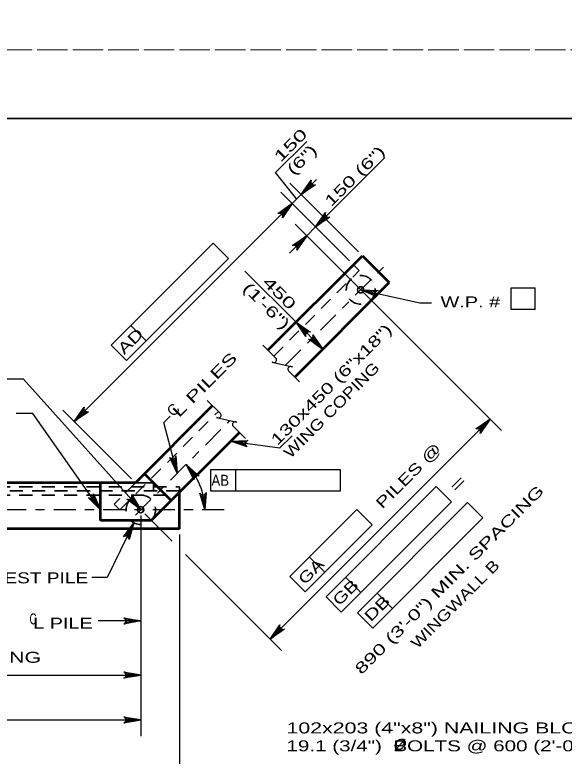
# Model space of a CAD drawing. Extents: x -6.4 to 73.1, y -66 to 0.
# Drawn here: x 16.4 to 22.39, y -29.71 to -21.62 of the extents above; entities that cross this region are included whole.
import ezdxf
from ezdxf.enums import TextEntityAlignment as Align

# ---------------------------------------------------------------- set-up
doc = ezdxf.new("R2010")
doc.units = 0
doc.header["$LTSCALE"] = 0.048
for name, pattern in [('DOT_DASHED', [7.7, 5, -1.2, 0.3, -1.2]), ('LONG_DASHED', [7.5, 6, -1.5]), ('MEDIUM_DASHED', [4.5, 3, -1.5])]:
    doc.linetypes.add(name, pattern=pattern)
for name, color, linetype, lineweight in [('1', 7, 'Continuous', 13), ('2', 7, 'Continuous', 53), ('4', 7, 'Continuous', 25), ('5', 7, 'Continuous', 25), ('63', 7, 'LONG_DASHED', 13)]:
    doc.layers.add(name, color=color, linetype=linetype, lineweight=lineweight)

msp = doc.modelspace()

# ---------------------------------------------------------------- hatches: boundary and pattern name
at = {"layer": '2'}
msp.add_hatch(color=256, dxfattribs=at).paths.add_polyline_path([(17.33158, -27.02208), (17.27175, -26.91983), (17.25558, -26.93108)])
at = {"layer": '4'}
for points in [[(20.171, -24.6215), (20.28425, -24.6565), (20.2885, -24.63725)], [(18.75042, -26.27408), (18.86608, -26.29992), (18.86875, -26.28042)], [(17.77042, -27.02208), (17.69892, -26.92758), (17.68425, -26.94067)]]:
    msp.add_hatch(color=256, dxfattribs=at).paths.add_polyline_path(points)
at = {"layer": '5'}
for points in [[(19.59108, -23.48475), (19.61892, -23.51258), (19.52142, -23.58217)], [(19.32658, -23.74925), (19.35442, -23.77708), (19.424, -23.67967)], [(19.74783, -23.83642), (19.77575, -23.86433), (19.67825, -23.93392)], [(19.48342, -24.10092), (19.51125, -24.12875), (19.58083, -24.03133)], [(19.56208, -25.04483), (19.53425, -25.07267), (19.46467, -24.97525)], [(19.68733, -25.17008), (19.6595, -25.19792), (19.75692, -25.2675)], [(17.11458, -25.96125), (17.14242, -25.98908), (17.04492, -26.05875)], [(21.48442, -26.10192), (21.51225, -26.12975), (21.58183, -26.03233)], [(18.15733, -26.50475), (18.11933, -26.51483), (18.1685, -26.624)], [(17.65225, -28.25575), (17.65225, -28.21642), (17.77042, -28.23608)], [(19.25083, -28.3355), (19.27867, -28.36333), (19.18125, -28.43292)], [(17.65225, -28.80667), (17.65225, -28.84608), (17.77042, -28.82633)], [(17.65225, -29.297), (17.65225, -29.33642), (17.77042, -29.31667)]]:
    msp.add_hatch(color=256, dxfattribs=at).paths.add_polyline_path(points)

# ---------------------------------------------------------------- linework, layer by layer
at = {"layer": '1', "lineweight": 35}
msp.add_lwpolyline([(1.75, -43.25), (33.25, -43.25), (33.25, -22.75), (1.75, -22.75)], close=True, dxfattribs=at)
at = {"layer": '2'}
for p, q in [((19.15867, -25.28117), (20.18958, -24.25033)), ((20.18958, -24.25033), (20.48183, -24.54258)), ((19.451, -25.5735), (20.48183, -24.54258)), ((17.71308, -26.72683), (18.55425, -25.88558)), ((17.88425, -27.14017), (18.84658, -26.17792)), ((18.10283, -26.92167), (17.8105, -26.62942)), ((17.71308, -26.72683), (7.85033, -26.72683)), ((17.33158, -27.14017), (17.33158, -26.72683)), ((18.19242, -27.22875), (18.19242, -26.832)), ((17.88425, -27.14017), (17.33158, -27.14017)), ((18.19242, -27.22875), (7.41692, -27.22875))]:
    msp.add_line(p, q, dxfattribs=at)
at = {"layer": '2', "lineweight": 25}
msp.add_lwpolyline([(17.33158, -27.02208), (16.59375, -25.97225), (16.40908, -25.97225)], dxfattribs=at)
msp.add_lwpolyline([(17.33158, -27.02208), (17.27175, -26.91983), (17.25558, -26.93108)], close=True, dxfattribs=at)
at = {"layer": '4', "linetype": 'MEDIUM_DASHED', "lineweight": 35}
for p, q in [((20.09217, -24.34775), (20.15475, -24.41042)), ((19.22133, -25.34383), (20.15475, -24.41042)), ((17.54308, -27.02208), (18.61692, -25.94825)), ((7.41692, -26.77275), (18.19242, -26.77275)), ((17.71308, -26.72683), (17.48042, -26.9595)), ((18.19242, -26.81542), (7.41692, -26.81542)), ((7.41692, -26.86133), (18.19242, -26.86133)), ((17.54308, -27.02208), (17.48042, -26.9595))]:
    msp.add_line(p, q, dxfattribs=at)
at = {"layer": '4', "lineweight": 35}
for p, q in [((17.90867, -26.72683), (17.71308, -26.72683)), ((17.90867, -26.81542), (17.90867, -26.72683)), ((18.19242, -26.832), (18.19242, -26.77275))]:
    msp.add_line(p, q, dxfattribs=at)
at = {"layer": '4'}
for points in [[(20.171, -24.6215), (20.81575, -24.7635), (20.94467, -24.7635)], [(17.77042, -27.02208), (16.49158, -25.59475), (16.30075, -25.59475)], [(18.75042, -26.27408), (19.28683, -26.34758), (19.42133, -26.21325)]]:
    msp.add_lwpolyline(points, dxfattribs=at)
for points in [[(20.171, -24.6215), (20.28425, -24.6565), (20.2885, -24.63725)], [(18.75042, -26.27408), (18.86608, -26.29992), (18.86875, -26.28042)], [(17.77042, -27.02208), (17.69892, -26.92758), (17.68425, -26.94067)]]:
    msp.add_lwpolyline(points, close=True, dxfattribs=at)
at = {"layer": '4', "linetype": 'MEDIUM_DASHED', "lineweight": 35}
for centre, radius in [((20.17105, -24.62149), 0.15748), ((17.77044, -27.02209), 0.16076)]:
    msp.add_circle(centre, radius, dxfattribs=at)
at = {"layer": '5'}
for p, q in [((19.67833, -23.93383), (20.435, -23.17717)), ((20.14608, -24.20683), (19.39617, -23.45692)), ((19.5215, -23.58217), (19.6885, -23.41517)), ((20.04867, -24.30425), (19.29875, -23.55433)), ((19.32658, -23.77708), (19.52142, -23.58217)), ((17.045, -26.05867), (19.424, -23.67967)), ((19.3405, -23.76317), (19.257, -23.84667)), ((20.04867, -24.30425), (19.553, -23.80858)), ((19.67825, -23.93392), (19.58083, -24.03133)), ((19.58083, -24.03133), (19.39225, -24.21992)), ((17.44725, -25.22467), (18.56083, -24.11117)), ((18.56083, -24.11117), (18.72783, -24.27817)), ((17.61433, -25.39175), (18.72783, -24.27817)), ((19.46467, -24.97525), (18.90508, -24.41567)), ((21.81158, -24.601), (22.07525, -24.601)), ((22.07525, -24.83725), (22.07525, -24.601)), ((19.48858, -24.95125), (19.58992, -24.84992)), ((19.75692, -25.26758), (19.46467, -24.97517)), ((17.66117, -25.01083), (17.82817, -25.17783)), ((19.78092, -25.24358), (19.88225, -25.14225)), ((17.44725, -25.22467), (17.61433, -25.39175)), ((19.101, -25.2235), (19.24442, -25.36692)), ((19.38183, -25.50425), (19.504, -25.6265)), ((18.49625, -25.8275), (18.63967, -25.971)), ((17.66958, -26.68333), (16.91967, -25.93342)), ((18.02225, -26.07025), (18.09158, -26.001)), ((19.18125, -28.43292), (21.58183, -26.03233)), ((18.1685, -26.624), (18.02225, -26.07025)), ((18.777, -26.10833), (18.913, -26.24433)), ((17.66958, -26.68333), (17.17392, -26.18767)), ((18.534, -26.58358), (19.946, -26.58358)), ((18.534, -26.81983), (18.534, -26.58358)), ((18.80775, -26.81983), (18.80775, -26.58358)), ((19.946, -26.58358), (19.946, -26.81983)), ((19.79192, -27.97125), (20.99458, -26.76858)), ((20.99458, -26.76858), (21.16158, -26.93567)), ((19.946, -26.81983), (18.534, -26.81983)), ((19.95892, -28.13825), (21.16158, -26.93567)), ((20.13475, -28.14683), (21.33742, -26.94417)), ((21.33742, -26.94417), (21.50442, -27.11125)), ((19.39633, -27.75175), (20.12992, -27.01808)), ((20.12992, -27.01808), (20.297, -27.18517)), ((17.77042, -27.08358), (17.77042, -29.49383)), ((17.814, -27.06558), (18.11467, -27.36633)), ((20.30183, -28.31383), (21.50442, -27.11125)), ((17.69492, -27.164), (17.40408, -27.75983)), ((19.56333, -27.91875), (20.297, -27.18517)), ((18.19242, -27.29033), (18.19242, -30.05967)), ((18.25933, -27.51092), (19.30658, -28.55825)), ((19.61017, -27.53783), (19.77725, -27.70492)), ((19.39633, -27.75175), (19.56333, -27.91875)), ((20.00575, -27.75733), (20.17283, -27.92442)), ((17.40408, -27.75983), (17.23592, -27.75983)), ((19.79192, -27.97125), (19.95892, -28.13825)), ((20.34867, -27.933), (20.51567, -28.1)), ((20.13475, -28.14683), (20.30183, -28.31383)), ((17.77042, -28.23608), (17.30583, -28.23608)), ((7.78525, -28.82633), (17.77042, -28.82633)), ((12.94308, -29.31667), (17.77042, -29.31667))]:
    msp.add_line(p, q, dxfattribs=at)
at = {"layer": '5', "linetype": 'DOT_DASHED'}
for p, q in [((19.34817, -25.44433), (20.42042, -24.37208)), ((17.71208, -27.08042), (18.744, -26.0485)), ((18.68125, -27.02208), (6.96517, -27.02208))]:
    msp.add_line(p, q, dxfattribs=at)
at = {"layer": '5', "lineweight": 35}
msp.add_line((20.54425, -29.64892), (20.65625, -29.52625), dxfattribs=at)
at = {"layer": '5'}
for points in [[(19.47258, -23.63108), (19.24133, -23.34033), (19.58133, -23.00033)], [(19.5215, -23.58217), (19.62858, -23.42567), (19.6255, -23.44283), (19.62908, -23.45692), (19.63642, -23.46725), (19.64675, -23.47458), (19.66083, -23.47817), (19.678, -23.47508), (19.5215, -23.58217), (19.66083, -23.47817), (19.64675, -23.47458), (19.5215, -23.58217), (19.63642, -23.46725), (19.62908, -23.45692), (19.5215, -23.58217), (19.6255, -23.44283)], [(19.424, -23.67967), (19.31692, -23.83617), (19.32, -23.819), (19.31642, -23.80492), (19.30908, -23.79458), (19.29875, -23.78725), (19.28467, -23.78367), (19.2675, -23.78675), (19.424, -23.67967), (19.28467, -23.78367), (19.29875, -23.78725), (19.424, -23.67967), (19.30908, -23.79458), (19.31642, -23.80492), (19.424, -23.67967), (19.32, -23.819)], [(19.67833, -23.93383), (19.78542, -23.77733), (19.78233, -23.7945), (19.78592, -23.80858), (19.79325, -23.81892), (19.80358, -23.82625), (19.81767, -23.82983), (19.83483, -23.82675), (19.67833, -23.93383), (19.81767, -23.82983), (19.80358, -23.82625), (19.67833, -23.93383), (19.79325, -23.81892), (19.78592, -23.80858), (19.67833, -23.93383), (19.78233, -23.7945)], [(19.45567, -23.90608), (20.61533, -25.06575), (21.70725, -26.15758)], [(19.58083, -24.03133), (19.47375, -24.18783), (19.47683, -24.17067), (19.47325, -24.15658), (19.46592, -24.14625), (19.45558, -24.13892), (19.4415, -24.13533), (19.42433, -24.13842), (19.58083, -24.03133), (19.4415, -24.13533), (19.45558, -24.13892), (19.58083, -24.03133), (19.46592, -24.14625), (19.47325, -24.15658), (19.58083, -24.03133), (19.47683, -24.17067)], [(22.07525, -24.83725), (21.81158, -24.83725), (21.81158, -24.601)], [(20.171, -24.6215), (20.36058, -24.6275), (20.34442, -24.63408), (20.3345, -24.64467), (20.32967, -24.65642), (20.32908, -24.66908), (20.33367, -24.68292), (20.3455, -24.69575), (20.171, -24.6215), (20.33367, -24.68292), (20.32908, -24.66908), (20.171, -24.6215), (20.32967, -24.65642), (20.3345, -24.64467), (20.171, -24.6215), (20.34442, -24.63408)], [(19.46467, -24.97517), (19.62117, -25.08233), (19.604, -25.07917), (19.58992, -25.08275), (19.5795, -25.09008), (19.57225, -25.10042), (19.56858, -25.1145), (19.57175, -25.13175), (19.46467, -24.97517), (19.56858, -25.1145), (19.57225, -25.10042), (19.46467, -24.97517), (19.5795, -25.09008), (19.58992, -25.08275), (19.46467, -24.97517), (19.604, -25.07917)], [(19.75692, -25.26758), (19.60042, -25.16042), (19.61758, -25.16358), (19.63167, -25.16), (19.64208, -25.15267), (19.64933, -25.14233), (19.653, -25.12825), (19.64983, -25.111), (19.75692, -25.26758), (19.653, -25.12825), (19.64933, -25.14233), (19.75692, -25.26758), (19.64208, -25.15267), (19.63167, -25.16), (19.75692, -25.26758), (19.61758, -25.16358)], [(19.217, -25.41442), (19.20325, -25.41125), (19.42483, -25.46183), (19.41, -25.45842)], [(17.045, -26.05867), (17.15208, -25.90217), (17.149, -25.91933), (17.15258, -25.93342), (17.15992, -25.94375), (17.17025, -25.95108), (17.18433, -25.95467), (17.2015, -25.95158), (17.045, -26.05867), (17.18433, -25.95467), (17.17025, -25.95108), (17.045, -26.05867), (17.15992, -25.94375), (17.15258, -25.93342), (17.045, -26.05867), (17.149, -25.91933)], [(18.61225, -26.0185), (18.5985, -26.01525), (18.82008, -26.06583), (18.80525, -26.0625)], [(21.58183, -26.03233), (21.47475, -26.18883), (21.47783, -26.17167), (21.47425, -26.15758), (21.46692, -26.14725), (21.45658, -26.13992), (21.4425, -26.13633), (21.42533, -26.13942), (21.58183, -26.03233), (21.4425, -26.13633), (21.45658, -26.13992), (21.58183, -26.03233), (21.46692, -26.14725), (21.47425, -26.15758), (21.58183, -26.03233), (21.47783, -26.17167)], [(18.75042, -26.27408), (18.93983, -26.26475), (18.92425, -26.27267), (18.91525, -26.28408), (18.91142, -26.29617), (18.91183, -26.30883), (18.9175, -26.32217), (18.93033, -26.334), (18.75042, -26.27408), (18.9175, -26.32217), (18.91183, -26.30883), (18.75042, -26.27408), (18.91142, -26.29617), (18.91525, -26.28408), (18.75042, -26.27408), (18.92425, -26.27267)], [(18.1685, -26.624), (18.08708, -26.45267), (18.10042, -26.464), (18.11433, -26.468), (18.127, -26.46692), (18.13858, -26.46158), (18.14875, -26.45125), (18.15467, -26.43483), (18.1685, -26.624), (18.14875, -26.45125), (18.13858, -26.46158), (18.1685, -26.624), (18.127, -26.46692), (18.11433, -26.468), (18.1685, -26.624), (18.10042, -26.464)], [(18.26433, -26.52825), (18.40608, -26.65433), (18.38933, -26.64908), (18.37492, -26.65083), (18.36375, -26.65683), (18.35517, -26.66617), (18.34983, -26.67967), (18.35075, -26.69708), (18.26433, -26.52825), (18.34983, -26.67967), (18.35517, -26.66617), (18.26433, -26.52825), (18.36375, -26.65683), (18.37492, -26.65083), (18.26433, -26.52825), (18.38933, -26.64908)], [(17.33158, -27.02208), (17.19583, -26.88967), (17.21217, -26.89567), (17.22667, -26.89458), (17.23817, -26.88917), (17.24717, -26.88017), (17.25308, -26.86692), (17.253, -26.8495), (17.33158, -27.02208), (17.25308, -26.86692), (17.24717, -26.88017), (17.33158, -27.02208), (17.23817, -26.88917), (17.22667, -26.89458), (17.33158, -27.02208), (17.21217, -26.89567)], [(17.77042, -27.02208), (17.62, -26.90658), (17.637, -26.91058), (17.65125, -26.90783), (17.662, -26.90108), (17.66983, -26.89108), (17.67425, -26.87725), (17.67208, -26.85992), (17.77042, -27.02208), (17.67425, -26.87725), (17.66983, -26.89108), (17.77042, -27.02208), (17.662, -26.90108), (17.65125, -26.90783), (17.77042, -27.02208), (17.637, -26.91058)], [(18.47, -27.02175), (18.41475, -26.84033), (18.42625, -26.8535), (18.43942, -26.8595), (18.45208, -26.86025), (18.46433, -26.85675), (18.47592, -26.848), (18.48425, -26.83267), (18.47, -27.02175), (18.47592, -26.848), (18.46433, -26.85675), (18.47, -27.02175), (18.45208, -26.86025), (18.43942, -26.8595), (18.47, -27.02175), (18.42625, -26.8535)], [(17.69492, -27.164), (17.64458, -27.34683), (17.64192, -27.32958), (17.63392, -27.31742), (17.62367, -27.31), (17.6115, -27.3065), (17.597, -27.30767), (17.58175, -27.31617), (17.69492, -27.164), (17.597, -27.30767), (17.6115, -27.3065), (17.69492, -27.164), (17.62367, -27.31), (17.63392, -27.31742), (17.69492, -27.164), (17.64192, -27.32958)], [(17.77042, -28.23608), (17.584, -28.271), (17.59833, -28.26108), (17.60575, -28.24858), (17.60792, -28.23608), (17.60575, -28.22358), (17.59833, -28.21108), (17.584, -28.20117), (17.77042, -28.23608), (17.59833, -28.21108), (17.60575, -28.22358), (17.77042, -28.23608), (17.60792, -28.23608), (17.60575, -28.24858), (17.77042, -28.23608), (17.59833, -28.26108)], [(19.18125, -28.43292), (19.28833, -28.27642), (19.28525, -28.29358), (19.28883, -28.30767), (19.29617, -28.318), (19.3065, -28.32533), (19.32058, -28.32892), (19.33775, -28.32583), (19.18125, -28.43292), (19.32058, -28.32892), (19.3065, -28.32533), (19.18125, -28.43292), (19.29617, -28.318), (19.28883, -28.30767), (19.18125, -28.43292), (19.28525, -28.29358)], [(17.77042, -28.82633), (17.584, -28.86125), (17.59833, -28.85133), (17.60575, -28.83883), (17.60792, -28.82633), (17.60575, -28.81383), (17.59833, -28.80133), (17.584, -28.79142), (17.77042, -28.82633), (17.59833, -28.80133), (17.60575, -28.81383), (17.77042, -28.82633), (17.60792, -28.82633), (17.60575, -28.83883), (17.77042, -28.82633), (17.59833, -28.85133)], [(17.77042, -29.31667), (17.584, -29.35158), (17.59833, -29.34167), (17.60575, -29.32917), (17.60792, -29.31667), (17.60575, -29.30417), (17.59833, -29.29167), (17.584, -29.28175), (17.77042, -29.31667), (17.59833, -29.29167), (17.60575, -29.30417), (17.77042, -29.31667), (17.60792, -29.31667), (17.60575, -29.32917), (17.77042, -29.31667), (17.59833, -29.34167)]]:
    msp.add_lwpolyline(points, dxfattribs=at)
for points in [[(19.59108, -23.48475), (19.61892, -23.51258), (19.52142, -23.58217)], [(19.32658, -23.74925), (19.35442, -23.77708), (19.424, -23.67967)], [(19.74783, -23.83642), (19.77575, -23.86433), (19.67825, -23.93392)], [(19.48342, -24.10092), (19.51125, -24.12875), (19.58083, -24.03133)], [(19.56208, -25.04483), (19.53425, -25.07267), (19.46467, -24.97525)], [(19.68733, -25.17008), (19.6595, -25.19792), (19.75692, -25.2675)], [(17.11458, -25.96125), (17.14242, -25.98908), (17.04492, -26.05875)], [(21.48442, -26.10192), (21.51225, -26.12975), (21.58183, -26.03233)], [(18.15733, -26.50475), (18.11933, -26.51483), (18.1685, -26.624)], [(17.65225, -28.25575), (17.65225, -28.21642), (17.77042, -28.23608)], [(19.25083, -28.3355), (19.27867, -28.36333), (19.18125, -28.43292)], [(17.65225, -28.80667), (17.65225, -28.84608), (17.77042, -28.82633)], [(17.65225, -29.297), (17.65225, -29.33642), (17.77042, -29.31667)]]:
    msp.add_lwpolyline(points, close=True, dxfattribs=at)
at = {"layer": '5', "lineweight": 35}
for centre in [(20.17105, -24.62149), (17.77044, -27.02209)]:
    msp.add_circle(centre, 0.03402, dxfattribs=at)
at = {"layer": '5'}
for centre, radius, start, end in [((19.22441, -25.38701), 0.02841, 255, 45), ((19.40372, -25.48613), 0.02841, 77.13276, 219.67141), ((18.61963, -25.99106), 0.02841, 255, 45), ((18.79895, -26.09018), 0.02841, 77.13276, 219.67141), ((17.77719, -27.02209), 0.69288, 0.00094, 45.39398)]:
    msp.add_arc(centre, radius, start, end, dxfattribs=at)
at = {"layer": '5', "lineweight": 35}
msp.add_spline([(20.64467, -29.53842), (20.63592, -29.5315), (20.62717, -29.52917), (20.61617, -29.52817), (20.60992, -29.52817), (20.59917, -29.53067), (20.58925, -29.53517), (20.58242, -29.539), (20.56917, -29.54967), (20.55875, -29.56317), (20.5525, -29.57575), (20.54892, -29.58742), (20.54775, -29.59817), (20.54892, -29.60742), (20.55342, -29.6205), (20.55817, -29.62742), (20.56775, -29.63467), (20.58225, -29.63817), (20.59875, -29.63767), (20.61967, -29.62817), (20.63492, -29.615), (20.64642, -29.59917), (20.65392, -29.5825), (20.65642, -29.56417), (20.65317, -29.55225), (20.64517, -29.53842)], degree=3, dxfattribs=at)
at = {"layer": '63'}
for points in [[(0, -22), (34, -22), (34, 0), (0, 0)], [(0, -44), (34, -44), (34, -22), (0, -22)]]:
    msp.add_lwpolyline(points, close=True, dxfattribs=at)

# ---------------------------------------------------------------- texts
at = {"layer": '5'}
for s, width, p in [('150', 1.6, (19.29517, -23.23608)), ('(6")', 1.5, (19.43658, -23.3775)), ('130x450 (6"x18")', 1.45, (19.26133, -26.32625)), ('L PILES', 1.55, (18.18725, -26.021)), ('WING COPING', 1.25, (19.40275, -26.46767))]:
    msp.add_text(s, height=0.12, rotation=45, dxfattribs=dict(at, width=width)).set_placement(p)
for s, rotation, width, p in [('150 (6")', 45, 1.5, (20.14749, -23.42176)), ('(1\'-6")', 315, 1.5, (19.09991, -24.83991)), ('450', 315, 1.6, (19.24132, -24.69849)), ('AD', 45, 1.4, (17.69987, -25.22413)), ('PILES @', 44.938, 1.4, (20.73441, -26.69337)), ('=', 44.938, 1.85, (21.27299, -26.77881)), ('890 (3\'-0") MIN. SPACING', 45, 1.5, (21.17999, -27.82709)), ('GA', 44.938, 1.35, (19.6712, -27.73729)), ('WINGWALL B', 45, 1.25, (21.2427, -28.09405)), ('GB', 44.938, 1.35, (20.04779, -27.96745)), ('DB', 44.938, 1.4, (20.39204, -28.1417))]:
    msp.add_text(s, height=0.12, rotation=rotation, dxfattribs=dict(at, width=width)).set_placement(p, align=Align.CENTER)
for s, width, p in [('W.P. #', 1.35, (21.36712, -24.81325)), ('AB', 0.9, (18.63733, -26.7605))]:
    msp.add_text(s, height=0.12, dxfattribs=dict(at, width=width)).set_placement(p, align=Align.CENTER)
msp.add_text('C', height=0.12, rotation=45, dxfattribs=at).set_placement((18.126, -26.01425))
for s, width, p in [('TEST PILE', 1.3, (16.15408, -27.8255)), ('C', 0.65, (16.55675, -28.27317)), ('L PILE', 1.35, (16.59583, -28.3205)), ('890 (3\'-0")MIN. SPACING', 1.45, (14.0085, -28.6925)), ('102x203 (4"x8") NAILING BLOCKS.  ', 1.45, (19.36058, -29.46342)), ('19.1 (3/4")  BOLTS @ 600 (2\'-0")', 1.4, (19.36058, -29.65917))]:
    msp.add_text(s, height=0.12, dxfattribs=dict(at, width=width)).set_placement(p)

doc.saveas('drawing.dxf')
